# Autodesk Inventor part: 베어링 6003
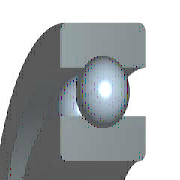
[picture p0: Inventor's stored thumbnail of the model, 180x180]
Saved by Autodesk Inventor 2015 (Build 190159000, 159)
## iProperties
Created: 2012-02
Part Number: 베어링 6003
Material: 강철, 연강
Description: 깊은 그루브 볼 베어링
Document SubType Name: Modeling
Standard: KS B 2023
Designer: mduedu
Standards Organization: KS
Language: ko-KR
Size Designation: 6003 - 17 x 35 x 10
Categories: <MemberInstance><Categories><Category DisplayName="샤프트 부품" InternalName="7f7aeb1f-a693-4053-b835-cee3144e0d98" Mnemonic="SHFT"><Category DisplayName="베어링" Inter
Density: 1 g/cm^3
Appearance: 노란색
IsCustomPart: 1
Author: mduedu
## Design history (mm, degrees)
sketch "스케치" dims "d0" = 4.68 (= -0.26 x WD + 0.26 x BD)
  geometry: L1 (2.66, 13)-(7.34, 13); L2 (5, 13)-(5, 10.66); L3 (5, 13)-(5, 15.34); L4 (3.261, 11.434)-(0, 11.434); L5 (0, 8.5)-(10, 8.5); L6 (3.261, 14.566)-(0, 14.566); L7 (0, 17.5)-(10, 17.5); L8 (10, 8.5)-(10, 11.434); L9 (6.739, 11.434)-(10, 11.434); L10 (6.739, 14.566)-(10, 14.566); L11 (10, 17.5)-(10, 14.566); L12 (-1.4, 0)-(8.4, 0) reference; L13 (0, -0.3)-(0, 5.3) reference
  constraints: 22 end point, 4 point on line, 2 collinear, 2 perpendicular, 2 symmetric about line, 1 midpoint, 1 parallel, 14 other
  dimensions: "d9" = 17 diameter of L5 L12 (= WD); "d11" = 35 diameter of L7 L12 (= BD); "d12" = 10 distance between parallel lines of L8 L13 (= KB); "d13" = 22.868 diameter of L9 L12 (= 0.326 x BD + 0.674 x WD)
revolve "본체" stored, may be unused: angle "d6" = 90 deg
revolve "볼" stored, may be unused: angle "d7" = 90 deg
pattern_circular "IDS_ARRAYBALL[SIMPL:T]" dims angle "d3" = 360 deg
body "Solid1"
fillet "모깎기1" dims "d1" = 0.3 (= KRS)
other parameters: "WD" = 17 [user parameter; used in 5 equation terms], "BD" = 35 [user parameter; used in 5 equation terms], "KB" = 10 [user parameter; used in 1 equation term], "KRS" = 0.3 [user parameter; used in 1 equation term], "d4" = 0, "d5" = 0, "d8" = 0, "d14" = 0, "d15" = 0, "BBA" = 0 [user parameter], "BC0" = 3250000 [user parameter], "BC" = 6050000 [user parameter], "BR" = 17.5 (= 0.5 x BD) [user parameter], "WR" = 8.5 (= 0.5 x WD) [user parameter]
